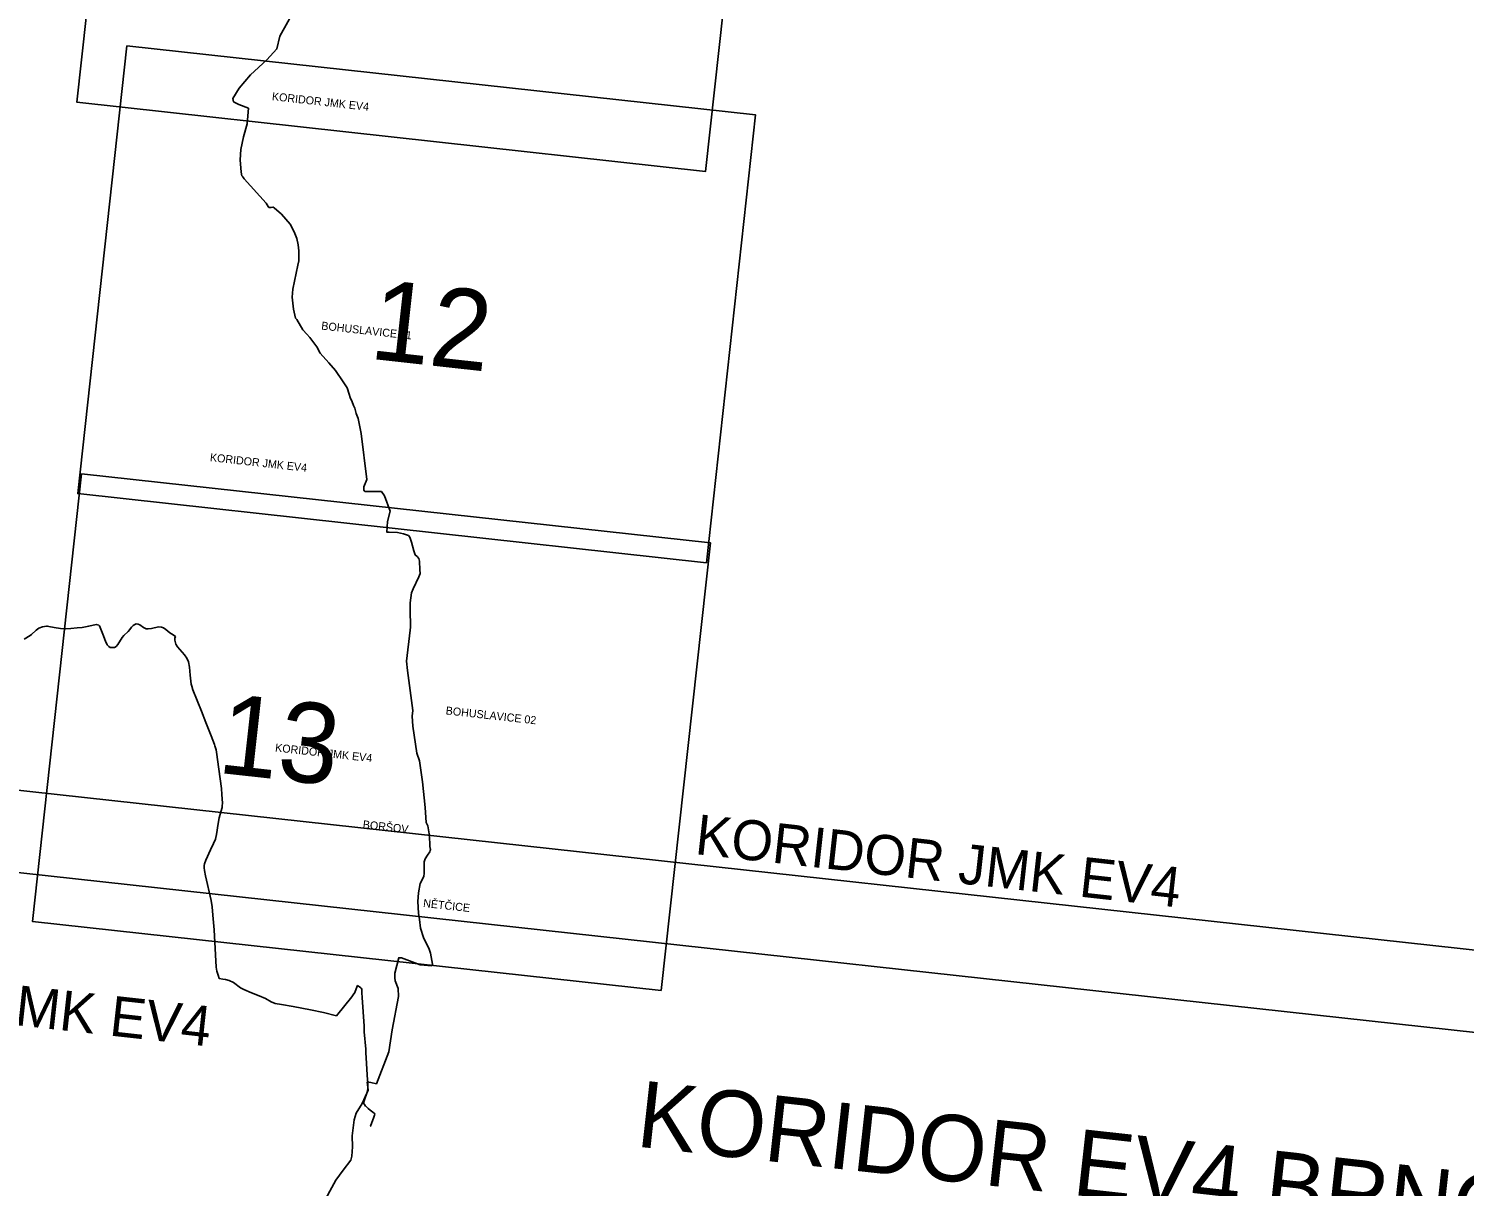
# Model space of a CAD drawing. Extents: x -678204 to -526855, y -1228851 to -1110393.
# Drawn here: x -565196 to -554430, y -1185682 to -1177001 of the extents above; entities that cross this region are included whole.
import ezdxf

# ---------------------------------------------------------------- set-up
doc = ezdxf.new("R2010")
doc.units = 0
for name, color, linetype in [('00_n_cyklo popisy', 7, 'Continuous'), ('00_n_cyklo popisy detaily', 7, 'Continuous'), ('00_n_cyklo prujezdne podminecne rekreacni hlavni', 7, 'Continuous'), ('00_n_cyklo prujezdne rekreacni hlavni', 7, 'Continuous'), ('00_n_cyklo prujezdne rekreacni vedlejsi', 7, 'Continuous'), ('00_n_cyklo trasovani rekreacni hlavni', 7, 'Continuous'), ('00_n_cyklo trasovani rekreacni vedlejsi', 7, 'Continuous'), ('00_n_legenda popisy_hlavni', 7, 'Continuous'), ('_HELP', 7, 'Continuous'), ('_HELP BIG', 7, 'Continuous')]:
    doc.layers.add(name, color=color, linetype=linetype)

msp = doc.modelspace()

# ---------------------------------------------------------------- linework, layer by layer
at = {"layer": '00_n_cyklo prujezdne podminecne rekreacni hlavni'}
for points in [[(-563664, -1177524), (-563659, -1177549), (-563621, -1177569), (-563548, -1177598), (-563558, -1177715), (-563585, -1177811), (-563605, -1177906), (-563610, -1177985), (-563603, -1178078), (-563597, -1178104), (-563591, -1178113), (-563581, -1178127), (-563415, -1178309), (-563400, -1178335), (-563394, -1178342), (-563389, -1178343), (-563380, -1178343), (-563363, -1178339), (-563355, -1178344), (-563301, -1178393), (-563236, -1178466), (-563205, -1178524), (-563185, -1178574), (-563174, -1178622), (-563169, -1178668), (-563169, -1178716), (-563171, -1178742), (-563177, -1178775), (-563216, -1178955), (-563219, -1179014), (-563215, -1179060), (-563211, -1179104), (-563194, -1179173), (-563186, -1179182), (-563139, -1179260), (-563111, -1179292), (-563087, -1179318), (-563036, -1179388), (-563010, -1179435), (-562944, -1179507), (-562896, -1179565), (-562837, -1179650), (-562808, -1179694), (-562793, -1179743), (-562786, -1179768), (-562769, -1179800), (-562760, -1179827), (-562749, -1179847), (-562739, -1179887), (-562726, -1179924), (-562702, -1180037), (-562660, -1180382), (-562682, -1180436), (-562682, -1180461), (-562676, -1180472)], [(-562335, -1181512), (-562362, -1181744), (-562354, -1181814), (-562314, -1182114), (-562320, -1182157), (-562315, -1182231), (-562285, -1182433), (-562264, -1182491), (-562243, -1182650), (-562222, -1182842), (-562216, -1182953), (-562204, -1182978), (-562192, -1183040), (-562188, -1183108), (-562189, -1183124), (-562187, -1183134), (-562184, -1183156), (-562186, -1183165), (-562189, -1183174), (-562205, -1183200), (-562224, -1183227), (-562230, -1183248), (-562230, -1183270), (-562229, -1183335), (-562233, -1183358), (-562259, -1183411), (-562273, -1183481), (-562278, -1183547), (-562272, -1183635), (-562266, -1183681)]]:
    msp.add_lwpolyline(points, dxfattribs=at)
at = {"layer": '00_n_cyklo prujezdne rekreacni hlavni'}
for points in [[(-562836, -1176328), (-562834, -1176473), (-562847, -1176546), (-562899, -1176674), (-562992, -1176735), (-563061, -1176751), (-563205, -1176864), (-563312, -1177057), (-563335, -1177153), (-563409, -1177235), (-563533, -1177347), (-563618, -1177448), (-563664, -1177524), (-563664, -1177524)], [(-562676, -1180472), (-562592, -1180472), (-562551, -1180473), (-562528, -1180505), (-562486, -1180620), (-562504, -1180698), (-562510, -1180778), (-562493, -1180778), (-562431, -1180779), (-562386, -1180789), (-562348, -1180802), (-562337, -1180814), (-562325, -1180852), (-562307, -1180916), (-562298, -1180948), (-562283, -1180960), (-562270, -1180974), (-562266, -1180995), (-562262, -1181059), (-562261, -1181087), (-562269, -1181112), (-562312, -1181203), (-562325, -1181232), (-562334, -1181307), (-562335, -1181357), (-562332, -1181489), (-562335, -1181512)], [(-562266, -1183681), (-562258, -1183746), (-562234, -1183817), (-562193, -1183905), (-562182, -1183933), (-562167, -1184017), (-562173, -1184028), (-562260, -1184022), (-562400, -1183968), (-562421, -1183969), (-562449, -1184084), (-562451, -1184118), (-562448, -1184142), (-562425, -1184200), (-562422, -1184258), (-562470, -1184509), (-562496, -1184674), (-562588, -1184913)], [(-562588, -1184913), (-562629, -1184904), (-562657, -1184900), (-562651, -1184961), (-562695, -1185062), (-562739, -1185134), (-562755, -1185185), (-562769, -1185305), (-562767, -1185386), (-562772, -1185456), (-562781, -1185487), (-562837, -1185561), (-562892, -1185636), (-562999, -1185834)]]:
    msp.add_lwpolyline(points, dxfattribs=at)
at = {"layer": '00_n_cyklo prujezdne rekreacni vedlejsi'}
for points in [[(-564096, -1181559), (-564112, -1181547), (-564137, -1181533), (-564167, -1181507), (-564186, -1181495), (-564201, -1181489), (-564223, -1181488), (-564274, -1181499), (-564301, -1181503), (-564315, -1181501), (-564335, -1181491), (-564363, -1181472), (-564376, -1181467), (-564390, -1181465), (-564401, -1181469), (-564413, -1181476), (-564424, -1181489), (-564438, -1181508), (-564438, -1181508), (-564450, -1181522), (-564483, -1181553), (-564496, -1181566), (-564528, -1181619), (-564541, -1181635), (-564553, -1181641), (-564569, -1181643), (-564577, -1181642), (-564584, -1181641), (-564595, -1181634), (-564608, -1181621), (-564620, -1181594), (-564640, -1181542), (-564664, -1181479), (-564671, -1181474), (-564689, -1181469), (-564745, -1181481), (-564795, -1181492), (-564832, -1181495), (-564881, -1181499), (-564918, -1181503), (-564957, -1181500), (-565004, -1181492), (-565045, -1181484), (-565054, -1181483), (-565062, -1181482), (-565093, -1181488), (-565119, -1181498), (-565141, -1181513), (-565175, -1181544), (-565186, -1181551), (-565230, -1181579)], [(-562631, -1185233), (-562632, -1185232), (-562607, -1185164), (-562602, -1185149), (-562599, -1185138), (-562606, -1185134), (-562635, -1185111), (-562650, -1185099), (-562668, -1185081), (-562669, -1185081), (-562677, -1185070), (-562686, -1185060), (-562680, -1185041), (-562657, -1184977), (-562654, -1184961), (-562652, -1184951), (-562653, -1184920), (-562653, -1184900), (-562654, -1184887), (-562667, -1184678), (-562668, -1184653), (-562679, -1184523), (-562680, -1184482), (-562694, -1184266), (-562697, -1184231), (-562698, -1184207), (-562700, -1184200), (-562704, -1184193), (-562715, -1184186), (-562729, -1184177), (-562739, -1184201), (-562751, -1184229), (-562763, -1184247), (-562772, -1184261), (-562888, -1184404), (-562984, -1184380), (-563083, -1184359), (-563212, -1184335), (-563300, -1184320), (-563347, -1184312), (-563377, -1184300), (-563421, -1184275), (-563467, -1184253), (-563526, -1184232), (-563582, -1184207), (-563608, -1184194), (-563659, -1184155), (-563692, -1184139), (-563721, -1184131), (-563740, -1184129), (-563767, -1184123), (-563776, -1184099), (-563786, -1184068), (-563790, -1184040), (-563794, -1183946), (-563805, -1183759), (-563814, -1183649), (-563820, -1183587), (-563828, -1183538), (-563869, -1183355), (-563877, -1183315), (-563880, -1183293), (-563879, -1183277), (-563877, -1183264), (-563867, -1183237), (-563833, -1183159), (-563809, -1183112), (-563795, -1183080), (-563792, -1183067), (-563788, -1183043), (-563776, -1182961), (-563768, -1182919), (-563756, -1182875), (-563746, -1182841), (-563744, -1182828), (-563743, -1182809), (-563748, -1182744), (-563751, -1182700), (-563769, -1182553), (-563787, -1182427), (-563790, -1182409), (-563800, -1182379), (-563803, -1182368), (-563828, -1182305), (-563868, -1182204), (-563900, -1182120), (-563964, -1181959), (-563973, -1181933), (-563977, -1181918), (-563986, -1181850), (-563991, -1181790), (-563998, -1181750), (-564010, -1181722), (-564027, -1181696), (-564080, -1181636), (-564092, -1181618), (-564099, -1181586), (-564099, -1181571), (-564096, -1181559), (-564112, -1181547), (-564137, -1181533), (-564167, -1181507), (-564186, -1181495), (-564201, -1181489), (-564223, -1181488), (-564274, -1181499), (-564301, -1181503), (-564315, -1181501), (-564335, -1181491), (-564363, -1181472), (-564376, -1181467), (-564390, -1181465), (-564401, -1181469), (-564413, -1181476), (-564424, -1181489), (-564438, -1181508), (-564438, -1181508), (-564450, -1181522), (-564483, -1181553), (-564496, -1181566), (-564528, -1181619), (-564541, -1181635), (-564553, -1181641), (-564569, -1181643), (-564577, -1181642), (-564584, -1181641), (-564595, -1181634), (-564608, -1181621), (-564620, -1181594), (-564640, -1181542), (-564664, -1181479), (-564671, -1181474), (-564689, -1181469), (-564745, -1181481), (-564795, -1181492), (-564832, -1181495), (-564881, -1181499), (-564918, -1181503), (-564957, -1181500), (-565004, -1181492), (-565045, -1181484), (-565054, -1181483), (-565062, -1181482), (-565093, -1181488), (-565119, -1181498), (-565141, -1181513), (-565175, -1181544), (-565186, -1181551), (-565230, -1181579)]]:
    msp.add_lwpolyline(points, dxfattribs=at)
at = {"layer": '00_n_cyklo trasovani rekreacni hlavni'}
for points in [[(-562836, -1176328), (-562834, -1176473), (-562847, -1176546), (-562899, -1176674), (-562992, -1176735), (-563061, -1176751), (-563205, -1176864), (-563312, -1177057), (-563335, -1177153), (-563409, -1177235), (-563533, -1177347), (-563618, -1177448), (-563664, -1177524), (-563664, -1177524)], [(-563664, -1177524), (-563659, -1177549), (-563621, -1177569), (-563548, -1177598), (-563558, -1177715), (-563585, -1177811), (-563605, -1177906), (-563610, -1177985), (-563603, -1178078), (-563597, -1178104), (-563591, -1178113), (-563581, -1178127), (-563415, -1178309), (-563400, -1178335), (-563394, -1178342), (-563389, -1178343), (-563380, -1178343), (-563363, -1178339), (-563355, -1178344), (-563301, -1178393), (-563236, -1178466), (-563205, -1178524), (-563185, -1178574), (-563174, -1178622), (-563169, -1178668), (-563169, -1178716), (-563171, -1178742), (-563177, -1178775), (-563216, -1178955), (-563219, -1179014), (-563215, -1179060), (-563211, -1179104), (-563194, -1179173), (-563186, -1179182), (-563139, -1179260), (-563111, -1179292), (-563087, -1179318), (-563036, -1179388), (-563010, -1179435), (-562944, -1179507), (-562896, -1179565), (-562837, -1179650), (-562808, -1179694), (-562793, -1179743), (-562786, -1179768), (-562769, -1179800), (-562760, -1179827), (-562749, -1179847), (-562739, -1179887), (-562726, -1179924), (-562702, -1180037), (-562660, -1180382), (-562682, -1180436), (-562682, -1180461), (-562676, -1180472)], [(-562676, -1180472), (-562592, -1180472), (-562551, -1180473), (-562528, -1180505), (-562486, -1180620), (-562504, -1180698), (-562510, -1180778), (-562493, -1180778), (-562431, -1180779), (-562386, -1180789), (-562348, -1180802), (-562337, -1180814), (-562325, -1180852), (-562307, -1180916), (-562298, -1180948), (-562283, -1180960), (-562270, -1180974), (-562266, -1180995), (-562262, -1181059), (-562261, -1181087), (-562269, -1181112), (-562312, -1181203), (-562325, -1181232), (-562334, -1181307), (-562335, -1181357), (-562332, -1181489), (-562335, -1181512)], [(-562335, -1181512), (-562362, -1181744), (-562354, -1181814), (-562314, -1182114), (-562320, -1182157), (-562315, -1182231), (-562285, -1182433), (-562264, -1182491), (-562243, -1182650), (-562222, -1182842), (-562216, -1182953), (-562204, -1182978), (-562192, -1183040), (-562188, -1183108), (-562189, -1183124), (-562187, -1183134), (-562184, -1183156), (-562186, -1183165), (-562189, -1183174), (-562205, -1183200), (-562224, -1183227), (-562230, -1183248), (-562230, -1183270), (-562229, -1183335), (-562233, -1183358), (-562259, -1183411), (-562273, -1183481), (-562278, -1183547), (-562272, -1183635), (-562266, -1183681)], [(-562266, -1183681), (-562258, -1183746), (-562234, -1183817), (-562193, -1183905), (-562182, -1183933), (-562167, -1184017), (-562173, -1184028), (-562260, -1184022), (-562400, -1183968), (-562421, -1183969), (-562449, -1184084), (-562451, -1184118), (-562448, -1184142), (-562425, -1184200), (-562422, -1184258), (-562470, -1184509), (-562496, -1184674), (-562588, -1184913)], [(-562588, -1184913), (-562629, -1184904), (-562657, -1184900), (-562651, -1184961), (-562695, -1185062), (-562739, -1185134), (-562755, -1185185), (-562769, -1185305), (-562767, -1185386), (-562772, -1185456), (-562781, -1185487), (-562837, -1185561), (-562892, -1185636), (-562999, -1185834)]]:
    msp.add_lwpolyline(points, dxfattribs=at)
at = {"layer": '00_n_cyklo trasovani rekreacni vedlejsi'}
for points in [[(-562631, -1185233), (-562632, -1185232), (-562607, -1185164), (-562602, -1185149), (-562599, -1185138), (-562606, -1185134), (-562635, -1185111), (-562650, -1185099), (-562668, -1185081), (-562669, -1185081), (-562677, -1185070), (-562686, -1185060), (-562680, -1185041), (-562657, -1184977), (-562654, -1184961), (-562652, -1184951), (-562653, -1184920), (-562653, -1184900), (-562654, -1184887), (-562667, -1184678), (-562668, -1184653), (-562679, -1184523), (-562680, -1184482), (-562694, -1184266), (-562697, -1184231), (-562698, -1184207), (-562700, -1184200), (-562704, -1184193), (-562715, -1184186), (-562729, -1184177), (-562739, -1184201), (-562751, -1184229), (-562763, -1184247), (-562772, -1184261), (-562888, -1184404), (-562984, -1184380), (-563083, -1184359), (-563212, -1184335), (-563300, -1184320), (-563347, -1184312), (-563377, -1184300), (-563421, -1184275), (-563467, -1184253), (-563526, -1184232), (-563582, -1184207), (-563608, -1184194), (-563659, -1184155), (-563692, -1184139), (-563721, -1184131), (-563740, -1184129), (-563767, -1184123), (-563776, -1184099), (-563786, -1184068), (-563790, -1184040), (-563794, -1183946), (-563805, -1183759), (-563814, -1183649), (-563820, -1183587), (-563828, -1183538), (-563869, -1183355), (-563877, -1183315), (-563880, -1183293), (-563879, -1183277), (-563877, -1183264), (-563867, -1183237), (-563833, -1183159), (-563809, -1183112), (-563795, -1183080), (-563792, -1183067), (-563788, -1183043), (-563776, -1182961), (-563768, -1182919), (-563756, -1182875), (-563746, -1182841), (-563744, -1182828), (-563743, -1182809), (-563748, -1182744), (-563751, -1182700), (-563769, -1182553), (-563787, -1182427), (-563790, -1182409), (-563800, -1182379), (-563803, -1182368), (-563828, -1182305), (-563868, -1182204), (-563900, -1182120), (-563964, -1181959), (-563973, -1181933), (-563977, -1181918), (-563986, -1181850), (-563991, -1181790), (-563998, -1181750), (-564010, -1181722), (-564027, -1181696), (-564080, -1181636), (-564092, -1181618), (-564099, -1181586), (-564099, -1181571), (-564096, -1181559), (-564112, -1181547), (-564137, -1181533), (-564167, -1181507), (-564186, -1181495), (-564201, -1181489), (-564223, -1181488), (-564274, -1181499), (-564301, -1181503), (-564315, -1181501), (-564335, -1181491), (-564363, -1181472), (-564376, -1181467), (-564390, -1181465), (-564401, -1181469), (-564413, -1181476), (-564424, -1181489), (-564438, -1181508), (-564438, -1181508), (-564450, -1181522), (-564483, -1181553), (-564496, -1181566), (-564528, -1181619), (-564541, -1181635), (-564553, -1181641), (-564569, -1181643), (-564577, -1181642), (-564584, -1181641), (-564595, -1181634), (-564608, -1181621), (-564620, -1181594), (-564640, -1181542), (-564664, -1181479), (-564671, -1181474), (-564689, -1181469), (-564745, -1181481), (-564795, -1181492), (-564832, -1181495), (-564881, -1181499), (-564918, -1181503), (-564957, -1181500), (-565004, -1181492), (-565045, -1181484), (-565054, -1181483), (-565062, -1181482), (-565093, -1181488), (-565119, -1181498), (-565141, -1181513), (-565175, -1181544), (-565186, -1181551), (-565230, -1181579)], [(-564096, -1181559), (-564112, -1181547), (-564137, -1181533), (-564167, -1181507), (-564186, -1181495), (-564201, -1181489), (-564223, -1181488), (-564274, -1181499), (-564301, -1181503), (-564315, -1181501), (-564335, -1181491), (-564363, -1181472), (-564376, -1181467), (-564390, -1181465), (-564401, -1181469), (-564413, -1181476), (-564424, -1181489), (-564438, -1181508), (-564438, -1181508), (-564450, -1181522), (-564483, -1181553), (-564496, -1181566), (-564528, -1181619), (-564541, -1181635), (-564553, -1181641), (-564569, -1181643), (-564577, -1181642), (-564584, -1181641), (-564595, -1181634), (-564608, -1181621), (-564620, -1181594), (-564640, -1181542), (-564664, -1181479), (-564671, -1181474), (-564689, -1181469), (-564745, -1181481), (-564795, -1181492), (-564832, -1181495), (-564881, -1181499), (-564918, -1181503), (-564957, -1181500), (-565004, -1181492), (-565045, -1181484), (-565054, -1181483), (-565062, -1181482), (-565093, -1181488), (-565119, -1181498), (-565141, -1181513), (-565175, -1181544), (-565186, -1181551), (-565230, -1181579)]]:
    msp.add_lwpolyline(points, dxfattribs=at)
at = {"layer": '_HELP'}
for points in [[(-564465, -1174195), (-559751, -1174713), (-560120, -1178071), (-564834, -1177553)], [(-564460, -1177131), (-559745, -1177648), (-560114, -1181006), (-564828, -1180488)], [(-564799, -1180339), (-560084, -1180856), (-560453, -1184214), (-565168, -1183696)]]:
    msp.add_lwpolyline(points, close=True, dxfattribs=at)
at = {"layer": '_HELP BIG'}
for points in [[(-544827, -1185575), (-573114, -1182469), (-570902, -1162324), (-542615, -1165430)], [(-546972, -1205110), (-575259, -1202004), (-573047, -1181859), (-544760, -1184965)]]:
    msp.add_lwpolyline(points, close=True, dxfattribs=at)

# ---------------------------------------------------------------- texts
at = {"layer": '00_n_cyklo popisy'}
for p in [(-560206, -1183190), (-567478, -1184232)]:
    msp.add_text('KORIDOR JMK EV4', height=300, rotation=353.6836, dxfattribs=at).set_placement(p)
at = {"layer": '00_n_cyklo popisy detaily'}
for s, p in [('KORIDOR JMK EV4', (-563374, -1177537)), ('BOHUSLAVICE 01', (-563004, -1179257)), ('KORIDOR JMK EV4', (-563839, -1180244)), ('BOHUSLAVICE 02', (-562071, -1182143)), ('KORIDOR JMK EV4', (-563350, -1182421)), ('BORŠOV', (-562693, -1182997)), ('NĚTČICE', (-562240, -1183587))]:
    msp.add_text(s, height=60, rotation=353.6836, dxfattribs=at).set_placement(p)
at = {"layer": '00_n_legenda popisy_hlavni'}
msp.add_text('KORIDOR EV4 BRNO-SLAVKOV-KYJOV', height=497.66, rotation=353.6836, dxfattribs=at).set_placement((-560649, -1185383))
at = {"layer": '_HELP'}
for s, p in [('12', (-562649, -1179475)), ('13', (-563789, -1182580))]:
    msp.add_text(s, height=600, rotation=353.6836, dxfattribs=at).set_placement(p)

doc.saveas('drawing.dxf')
